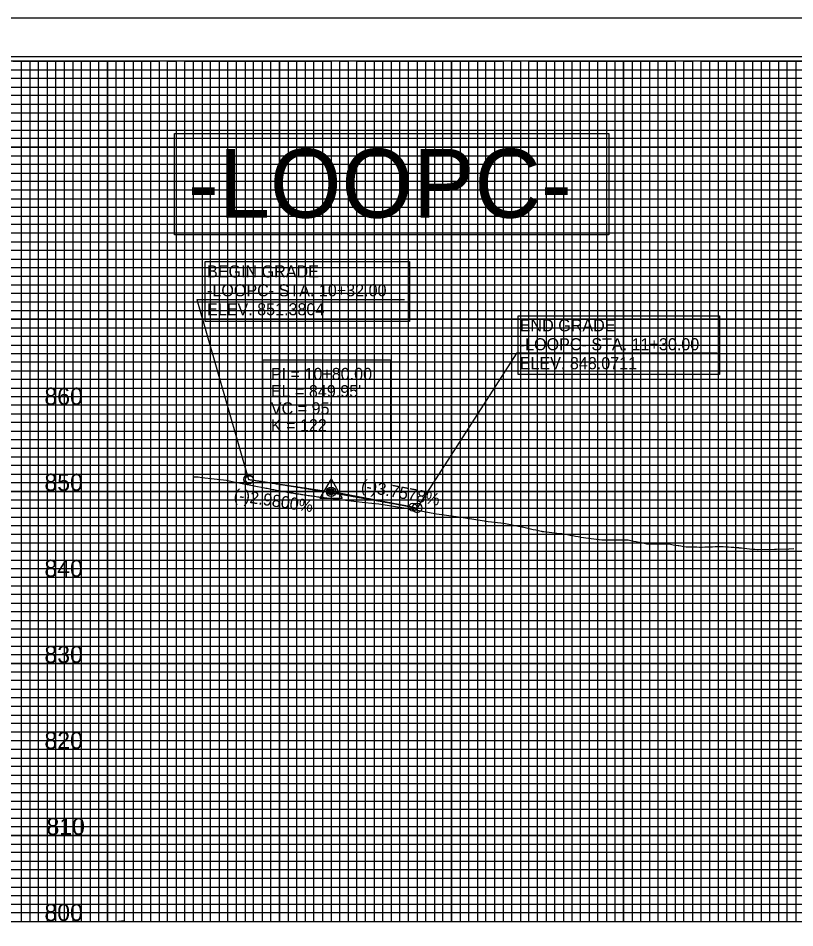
# Model space of a CAD drawing. Extents: x 570622 to 580296, y -55533 to -48575.
# Drawn here: x 571587 to 572038, y -54411 to -53883 of the extents above; entities that cross this region are included whole.
import ezdxf

# ---------------------------------------------------------------- set-up
doc = ezdxf.new("R2010")
doc.units = 0
for name, color, linetype in [('Default', 7, 'Continuous'), ('Exist Vertical Profile Ground Line', 7, 'Continuous'), ('Exist Vertical Profile Vertical Axis Label', 7, 'Continuous'), ('Prop Grid Mask', 7, 'Continuous'), ('Prop PFL VPI Symbol CELL', 7, 'Continuous'), ('Prop Vertical Profile Curve Label', 7, 'Continuous'), ('Prop Vertical Profile Grade', 7, 'Continuous'), ('Prop Vertical Profile Grade Label', 7, 'Continuous'), ('Prop VPI Label', 7, 'Continuous'), ('Sheet Cutting Line CELL', 7, 'Continuous'), ('Sheet Data Field CELL', 7, 'Continuous'), ('Sheet DOT Grid CELL', 7, 'Continuous'), ('Sheet Layout Profile Border Port 1', 7, 'Continuous'), ('Sheet Plot Border Inside CELL', 7, 'Continuous'), ('Sheet Plot Border Outside CELL', 7, 'Continuous'), ('Sheet Profile CELL', 7, 'Continuous'), ('Sheet Profile Grid Major CELL', 7, 'Continuous'), ('Sheet Profile Grid Middle CELL', 7, 'Continuous'), ('Sheet Profile Grid Minor CELL', 7, 'Continuous')]:
    doc.layers.add(name, color=color, linetype=linetype)

msp = doc.modelspace()

# ---------------------------------------------------------------- linework, layer by layer
at = {"layer": 'Exist Vertical Profile Ground Line'}
for points in [[(571688.69, -54149.28), (571691.43, -54149.22), (571691.49, -54149.22), (571693.67, -54149.67), (571707.85, -54151.26), (571711.92, -54152.09), (571729.96, -54155.63), (571730.73, -54155.79), (571731.5, -54155.94), (571732.27, -54156.08), (571733.04, -54156.23), (571733.82, -54156.38), (571734.59, -54156.53), (571735.36, -54156.68), (571736.13, -54156.82), (571736.9, -54156.97), (571737.67, -54157.11), (571738.44, -54157.25), (571739.22, -54157.4), (571739.99, -54157.54), (571740.76, -54157.68), (571741.53, -54157.82), (571742.3, -54157.96), (571743.07, -54158.09), (571743.84, -54158.23), (571743.86, -54158.23), (571744.61, -54158.37), (571745.39, -54158.5), (571746.16, -54158.64), (571746.26, -54158.65), (571746.93, -54158.76), (571747.7, -54158.88), (571748.47, -54158.99), (571749.24, -54159.11), (571750.01, -54159.22), (571750.78, -54159.34), (571751.05, -54159.38), (571751.56, -54159.45), (571752.33, -54159.57), (571753.1, -54159.69), (571753.87, -54159.8), (571754.64, -54159.92), (571755.41, -54160.03), (571756.18, -54160.14), (571756.96, -54160.26), (571757.73, -54160.37), (571758.5, -54160.47), (571759.27, -54160.58), (571760.04, -54160.69), (571760.81, -54160.79), (571761.58, -54160.9), (571762.35, -54161), (571763.13, -54161.1), (571763.9, -54161.2), (571764.63, -54161.3), (571764.67, -54161.3), (571765.44, -54161.39), (571766.21, -54161.48), (571766.98, -54161.57), (571767.75, -54161.65), (571768.52, -54161.74), (571770.69, -54161.98), (571781.89, -54163.36), (571788.29, -54164.13), (571796.44, -54164.98), (571812.14, -54167.51), (571816.7, -54168.21), (571830.01, -54170.73), (571833.08, -54171.1), (571846.76, -54173.06), (571857.6, -54174.88), (571858.26, -54174.94), (571868.98, -54176.2), (571879.58, -54178.36), (571879.84, -54178.4), (571886.17, -54179.81), (571887.7, -54180.15), (571889.23, -54180.49), (571890.77, -54180.84), (571891.07, -54180.9), (571891.37, -54180.96), (571892.3, -54181.06), (571893.83, -54181.23), (571895.36, -54181.41), (571896.9, -54181.58), (571898.43, -54181.75), (571899.96, -54181.92), (571901.5, -54182.1), (571902.46, -54182.21), (571902.83, -54182.27), (571903.03, -54182.3), (571904.56, -54182.59), (571906.09, -54182.87), (571907.63, -54183.16), (571909.16, -54183.44), (571910.69, -54183.73), (571912.23, -54184.01), (571913.33, -54184.22), (571913.68, -54184.28), (571913.76, -54184.29), (571915.29, -54184.47)], [(571915.29, -54184.47), (571916.82, -54184.66), (571918.36, -54184.85), (571919.89, -54185.04), (571921.42, -54185.23), (571922.96, -54185.42), (571924.49, -54185.6), (571926.02, -54185.79), (571926.24, -54185.82), (571926.45, -54185.84), (571927.55, -54185.84), (571929.09, -54185.85), (571930.62, -54185.85), (571932.15, -54185.86), (571933.69, -54185.87), (571935.22, -54185.87), (571936.75, -54185.88), (571938.28, -54185.88), (571939.82, -54185.88), (571940.9, -54185.89), (571940.97, -54185.9), (571941.35, -54185.97), (571942.88, -54186.28), (571944.42, -54186.58), (571945.95, -54186.88), (571947.48, -54187.18), (571947.94, -54187.27), (571949.01, -54187.49), (571950.55, -54187.81), (571951.98, -54188.11), (571952.08, -54188.11), (571952.17, -54188.12), (571953.61, -54188.12), (571955.15, -54188.12), (571955.63, -54188.12), (571956.68, -54188.13), (571958.21, -54188.14), (571959.74, -54188.16), (571961.28, -54188.17), (571962.81, -54188.19), (571964.05, -54188.2), (571964.19, -54188.2), (571964.34, -54188.22), (571965.88, -54188.46), (571967.41, -54188.7), (571968.94, -54188.94), (571970.47, -54189.19), (571970.84, -54189.24), (571972.01, -54189.43), (571973.54, -54189.69), (571975.02, -54189.93), (571975.07, -54189.93), (571975.16, -54189.93), (571976.61, -54189.95), (571978.14, -54189.97), (571979.67, -54189.99), (571981.2, -54190.02), (571982.74, -54190.04), (571984.27, -54190.07), (571984.34, -54190.07), (571984.36, -54190.07), (571985.8, -54190.02), (571987.08, -54189.97), (571987.34, -54189.96), (571988.23, -54189.93), (571988.87, -54189.91), (571990.4, -54189.87), (571991.93, -54189.82), (571993.47, -54189.78), (571994.82, -54189.74), (571994.88, -54189.74), (571995, -54189.75), (571996.53, -54189.84), (571998.07, -54189.93), (571999.6, -54190.03), (572001.13, -54190.13), (572002.66, -54190.23), (572004.2, -54190.33), (572005.5, -54190.42), (572005.51, -54190.42), (572005.73, -54190.44), (572006.54, -54190.52), (572007.26, -54190.59), (572008.8, -54190.75), (572010.33, -54190.91), (572011.86, -54191.07), (572013.39, -54191.23), (572014.93, -54191.39), (572016.46, -54191.54), (572016.72, -54191.57), (572016.8, -54191.57), (572026.45, -54191.35), (572027.45, -54191.36), (572034.71, -54191.13), (572037.64, -54190.99)]]:
    msp.add_lwpolyline(points, dxfattribs=at)
at = {"layer": 'Prop Grid Mask'}
for points in [[(571677.74, -53949.75), (571930.02, -53949.75), (571930.02, -54008.61), (571677.74, -54008.61)], [(571695.51, -54024.2), (571814.2, -54024.2), (571814.2, -54058.96), (571695.51, -54058.96)], [(571877.34, -54055.62), (571994.49, -54055.62), (571994.49, -54089.87), (571877.34, -54089.87)], [(571728.98, -54081.21), (571803.12, -54081.21), (571803.12, -54127.77), (571728.98, -54127.77)]]:
    msp.add_lwpolyline(points, close=True, dxfattribs=at)
at = {"layer": 'Prop PFL VPI Symbol CELL'}
for p, q in [((571768.68, -54150.46), (571762.23, -54161.66)), ((571768.68, -54150.46), (571775.18, -54161.66)), ((571762.23, -54161.66), (571775.18, -54161.66))]:
    msp.add_line(p, q, dxfattribs=at)
for radius in [1.75, 1.2]:
    msp.add_circle((571768.69, -54157.94), radius, dxfattribs=at)
at = {"layer": 'Prop Vertical Profile Curve Label'}
for centre in [(571721.19, -54150.86), (571816.19, -54166.87)]:
    msp.add_circle(centre, 2.25, dxfattribs=at)
at = {"layer": 'Prop Vertical Profile Grade'}
for p, q in [((571720.69, -54150.79), (571721.19, -54150.86)), ((571816.19, -54166.87), (571818.69, -54167.34))]:
    msp.add_line(p, q, dxfattribs=at)
msp.add_spline([(571721.19, -54150.86), (571723.09, -54151.15), (571724.99, -54151.43), (571726.89, -54151.72), (571728.79, -54152.01), (571730.69, -54152.3), (571732.59, -54152.59), (571734.49, -54152.88), (571736.39, -54153.18), (571738.29, -54153.47), (571740.19, -54153.77), (571742.09, -54154.07), (571743.99, -54154.37), (571745.89, -54154.67), (571747.79, -54154.97), (571749.69, -54155.28), (571751.59, -54155.58), (571753.49, -54155.89), (571755.39, -54156.2), (571757.29, -54156.51), (571759.19, -54156.82), (571761.09, -54157.14), (571762.99, -54157.45), (571764.89, -54157.77), (571766.79, -54158.08), (571768.69, -54158.4), (571770.59, -54158.72), (571772.49, -54159.05), (571774.39, -54159.37), (571776.29, -54159.7), (571778.19, -54160.02), (571780.09, -54160.35), (571781.99, -54160.68), (571783.89, -54161.01), (571785.79, -54161.34), (571787.69, -54161.68), (571789.59, -54162.01), (571791.49, -54162.35), (571793.39, -54162.69), (571795.29, -54163.03), (571797.19, -54163.37), (571799.09, -54163.71), (571800.99, -54164.06), (571802.89, -54164.4), (571804.79, -54164.75), (571806.69, -54165.1), (571808.59, -54165.45), (571810.49, -54165.8), (571812.39, -54166.16), (571814.29, -54166.51), (571816.19, -54166.87)], degree=3, dxfattribs=at)
at = {"layer": 'Prop VPI Label'}
for p, q in [((571690.66, -54046.22), (571811.31, -54046.22)), ((571690.66, -54046.22), (571720.69, -54150.79)), ((571876.67, -54077.25), (571818.69, -54167.34)), ((571876.67, -54077.25), (571992.95, -54077.25)), ((571721.19, -54150.86), (571765.97, -54157.54)), ((571816.19, -54166.87), (571771.39, -54158.45))]:
    msp.add_line(p, q, dxfattribs=at)
for centre in [(571720.69, -54150.79), (571768.69, -54157.94), (571818.69, -54167.34)]:
    msp.add_circle(centre, 2.75, dxfattribs=at)
at = {"layer": 'Sheet Cutting Line CELL'}
msp.add_line((572305.69, -53882.69), (570621.69, -53882.69), dxfattribs=at)
at = {"layer": 'Sheet DOT Grid CELL'}
for p, q in [((571588.69, -54407.69), (571588.69, -53907.69)), ((571638.69, -54407.69), (571638.69, -53907.69)), ((571688.69, -54407.69), (571688.69, -53907.69)), ((571738.69, -54407.69), (571738.69, -53907.69)), ((571788.69, -54407.69), (571788.69, -53907.69)), ((571838.69, -54407.69), (571838.69, -53907.69)), ((571888.69, -54407.69), (571888.69, -53907.69)), ((571938.69, -54407.69), (571938.69, -53907.69)), ((571988.69, -54407.69), (571988.69, -53907.69)), ((572088.64, -53957.69), (570788.69, -53957.69)), ((572088.64, -54007.69), (570788.69, -54007.69)), ((572288.69, -54057.69), (570788.69, -54057.69)), ((572288.69, -54107.69), (570788.69, -54107.69)), ((572288.69, -54157.69), (570788.69, -54157.69)), ((572288.69, -54207.69), (570788.69, -54207.69)), ((572288.69, -54257.69), (570788.69, -54257.69)), ((572288.69, -54307.69), (570788.69, -54307.69)), ((572288.69, -54357.69), (570788.69, -54357.69))]:
    msp.add_line(p, q, dxfattribs=at)
at = {"layer": 'Sheet Layout Profile Border Port 1'}
msp.add_lwpolyline([(570838.69, -53907.69), (570838.69, -54407.69), (572238.69, -54407.69), (572238.69, -54045.24), (572088.64, -54045.24), (572088.64, -53907.69)], close=True, dxfattribs=at)
at = {"layer": 'Sheet Plot Border Inside CELL'}
msp.add_lwpolyline([(570634.69, -54960.24), (572301.19, -54960.24), (572301.19, -53905.14), (570634.69, -53905.14)], close=True, dxfattribs=at)
at = {"layer": 'Sheet Plot Border Outside CELL'}
msp.add_lwpolyline([(570621.69, -54982.69), (572305.69, -54982.69), (572305.69, -53882.69), (570621.69, -53882.69)], close=True, dxfattribs=at)
at = {"layer": 'Sheet Profile CELL'}
msp.add_line((570788.69, -54407.69), (572288.69, -54407.69), dxfattribs=at)
msp.add_lwpolyline([(572288.69, -53907.69), (570788.69, -53907.69), (570788.69, -54957.69), (572288.69, -54957.69)], close=True, dxfattribs=at)
at = {"layer": 'Sheet Profile Grid Major CELL'}
for points in [[(571538.69, -54407.69), (571588.69, -54407.69), (571588.69, -53907.69), (571638.69, -53907.69), (571638.69, -54407.69), (571688.69, -54407.69), (571688.69, -53907.69), (571738.69, -53907.69), (571738.69, -54407.69), (571788.69, -54407.69), (571788.69, -53907.69), (571838.69, -53907.69), (571838.69, -54407.69), (571888.69, -54407.69), (571888.69, -53907.69), (571938.69, -53907.69), (571938.69, -54407.69), (571988.69, -54407.69), (571988.69, -53907.69), (572038.69, -53907.69), (572038.69, -54407.69), (572088.69, -54407.69), (572088.69, -53907.69), (572114.99, -53907.69)], [(570788.69, -53957.69), (572088.69, -53957.69)], [(572088.69, -54007.69), (570788.69, -54007.69), (570788.69, -54057.69), (572288.69, -54057.69)], [(572288.69, -54107.69), (570788.69, -54107.69), (570788.69, -54157.69), (572288.69, -54157.69)], [(572288.69, -54207.69), (570788.69, -54207.69), (570788.69, -54257.69), (572288.69, -54257.69)], [(572288.69, -54307.69), (570788.69, -54307.69), (570788.69, -54307.69), (570788.69, -54357.69), (572288.69, -54357.69)]]:
    msp.add_lwpolyline(points, dxfattribs=at)
at = {"layer": 'Sheet Profile Grid Middle CELL'}
msp.add_line((570788.69, -53932.69), (572088.64, -53932.69), dxfattribs=at)
for points in [[(571563.69, -54407.69), (571613.69, -54407.69), (571613.69, -53907.69), (571663.69, -53907.69), (571663.69, -54407.69), (571713.69, -54407.69), (571713.69, -53907.69), (571763.69, -53907.69), (571763.69, -54407.69), (571813.69, -54407.69), (571813.69, -53907.69), (571863.69, -53907.69), (571863.69, -54407.69), (571913.69, -54407.69), (571913.69, -53907.69), (571963.69, -53907.69), (571963.69, -54407.69), (572013.69, -54407.69), (572013.69, -53907.69), (572063.69, -53907.69), (572063.69, -54407.69), (572113.69, -54407.69), (572113.69, -54045.24)], [(572088.69, -53982.69), (570788.69, -53982.69), (570788.69, -54032.69), (572088.69, -54032.69)], [(572288.69, -54082.69), (570788.69, -54082.69), (570788.69, -54132.69), (572113.69, -54132.69)], [(572288.69, -54182.69), (570788.69, -54182.69), (570788.69, -54232.69), (572288.69, -54232.69)], [(572288.69, -54282.69), (570788.69, -54282.69), (570788.69, -54332.69), (572288.69, -54332.69)], [(572288.69, -54382.69), (570788.69, -54382.69)]]:
    msp.add_lwpolyline(points, dxfattribs=at)
at = {"layer": 'Sheet Profile Grid Minor CELL'}
for p, q in [((570838.69, -53912.69), (572088.69, -53912.69)), ((572088.69, -53917.69), (570838.69, -53918.04)), ((570838.69, -53922.69), (572088.69, -53922.69)), ((572088.64, -54042.69), (570838.69, -54042.69)), ((572238.69, -54047.69), (570838.69, -54047.69)), ((572238.69, -54052.69), (570838.69, -54052.69)), ((570838.69, -54062.69), (572238.69, -54062.69)), ((572238.69, -54067.69), (570838.69, -54067.69)), ((570838.69, -54072.69), (572238.69, -54072.69)), ((572238.69, -54092.69), (570838.69, -54092.69)), ((570838.69, -54097.69), (572238.69, -54097.69)), ((572238.69, -54117.69), (570838.69, -54117.69)), ((570838.69, -54122.69), (572238.69, -54122.69)), ((572238.69, -54142.69), (570838.69, -54142.69)), ((570838.69, -54147.69), (572238.69, -54147.69)), ((572238.69, -54152.69), (570838.69, -54152.69)), ((570838.69, -54162.69), (572238.69, -54162.69)), ((572238.69, -54167.69), (570838.69, -54167.69)), ((570838.69, -54172.69), (572238.69, -54172.69)), ((572238.69, -54177.69), (570838.69, -54177.69)), ((570838.69, -54187.69), (572238.69, -54187.69)), ((572238.69, -54192.69), (570838.69, -54192.69)), ((570838.69, -54197.69), (572238.69, -54197.69)), ((572238.69, -54202.69), (570838.69, -54202.69)), ((570838.69, -54212.69), (572238.69, -54212.69)), ((572238.69, -54217.69), (570838.69, -54217.69)), ((570838.69, -54222.69), (572238.69, -54222.69)), ((572238.69, -54227.69), (570838.69, -54227.69)), ((570838.69, -54237.69), (572238.69, -54237.69)), ((572238.69, -54242.69), (570838.69, -54242.69)), ((570838.69, -54247.69), (572238.69, -54247.69)), ((572238.69, -54252.69), (570838.69, -54252.69)), ((570838.69, -54262.69), (572238.69, -54262.69)), ((572238.69, -54267.69), (570838.69, -54267.69)), ((570838.69, -54272.69), (572238.69, -54272.69)), ((572238.69, -54277.69), (570838.69, -54277.69)), ((570838.69, -54287.69), (572238.69, -54287.69)), ((572238.69, -54292.69), (570838.69, -54292.69)), ((572238.69, -54297.69), (570838.69, -54297.69)), ((572238.69, -54302.69), (570838.69, -54302.69)), ((570838.69, -54312.69), (572238.69, -54312.69)), ((572238.69, -54317.69), (570838.69, -54317.69)), ((570838.69, -54322.69), (572238.69, -54322.69)), ((572238.69, -54327.69), (570838.69, -54327.69)), ((570838.69, -54337.69), (572238.69, -54337.69)), ((572238.69, -54342.69), (570838.69, -54342.69)), ((570838.69, -54347.69), (572238.69, -54347.69)), ((572238.69, -54352.69), (570838.69, -54352.69)), ((570838.69, -54362.69), (572238.69, -54362.69)), ((572238.69, -54367.69), (570838.69, -54367.69)), ((570838.69, -54372.69), (572238.69, -54372.69)), ((572238.69, -54377.69), (570838.69, -54377.69)), ((570838.69, -54387.69), (572238.69, -54387.69)), ((572238.69, -54392.69), (570838.69, -54392.69)), ((570838.69, -54397.69), (572238.69, -54397.69))]:
    msp.add_line(p, q, dxfattribs=at)
for points in [[(571583.69, -53907.69), (571593.69, -53907.69), (571593.69, -54407.69), (571598.69, -54407.69), (571598.69, -53907.69), (571603.69, -53907.69), (571603.69, -54407.69), (571608.69, -54407.69), (571608.69, -53907.69), (571618.69, -53907.69), (571618.69, -54407.69), (571623.69, -54407.69), (571623.69, -53907.69), (571628.69, -53907.69), (571628.69, -54407.69), (571633.69, -54407.69), (571633.69, -53907.69), (571643.69, -53907.69), (571643.69, -54407.69), (571648.39, -54407.14), (571648.69, -54407.69), (571648.69, -53907.69), (571653.69, -53907.69), (571653.69, -54407.69), (571658.69, -54407.69), (571658.69, -53907.69), (571668.69, -53907.69), (571668.69, -54407.69), (571673.69, -54407.69)], [(571673.69, -54407.69), (571673.69, -53907.69), (571678.69, -53907.69), (571678.69, -54407.69), (571683.69, -54407.69), (571683.69, -53907.69), (571693.69, -53907.69), (571693.69, -54407.69), (571698.69, -54407.69), (571698.69, -53907.69), (571703.69, -53907.69), (571703.69, -54407.69), (571708.69, -54407.69), (571708.69, -53907.69), (571718.69, -53907.69), (571718.69, -54407.69), (571723.69, -54407.69), (571723.69, -53907.69), (571728.69, -53907.69), (571728.69, -54407.69), (571733.69, -54407.69), (571733.69, -53907.69), (571743.69, -53907.69), (571743.69, -54407.69), (571748.69, -54407.69), (571748.69, -53907.69), (571753.69, -53907.69), (571753.69, -54407.69), (571758.69, -54407.69), (571758.69, -53907.69), (571768.69, -53907.69), (571768.69, -54407.69), (571773.69, -54407.69), (571773.69, -53907.69), (571778.69, -53907.69), (571778.69, -54407.69), (571783.69, -54407.69), (571783.69, -53907.69), (571793.69, -53907.69), (571793.69, -54407.69), (571798.69, -54407.69), (571798.69, -53907.69), (571803.69, -53907.69), (571803.69, -54407.69), (571808.69, -54407.69), (571808.69, -53907.69), (571818.69, -53907.69), (571818.69, -54407.69), (571823.69, -54407.69), (571823.69, -53907.69), (571828.69, -53907.69), (571828.69, -54407.69), (571833.69, -54407.69), (571833.69, -53907.69), (571843.69, -53907.69), (571843.69, -54407.69), (571848.69, -54407.69), (571848.69, -53907.69), (571853.69, -53907.69), (571853.69, -54407.69), (571858.69, -54407.69), (571858.69, -53907.69), (571868.69, -53907.69), (571868.69, -54407.69), (571873.69, -54407.69), (571873.69, -53907.69), (571878.69, -53907.69), (571878.69, -54407.69), (571883.69, -54407.69), (571883.69, -53907.69), (571893.69, -53907.69), (571893.69, -54407.69), (571898.69, -54407.69), (571898.69, -53907.69), (571903.69, -53907.69), (571903.69, -54407.69), (571908.69, -54407.69), (571908.69, -53907.69), (571918.69, -53907.69), (571918.69, -54407.69), (571923.69, -54407.69), (571923.69, -53907.69), (571928.69, -53907.69), (571928.69, -54407.69), (571933.69, -54407.69), (571933.69, -53907.69), (571943.69, -53907.69), (571943.69, -54407.69), (571948.69, -54407.69), (571948.69, -53907.69), (571953.69, -53907.69), (571953.69, -54407.69), (571958.69, -54407.69), (571958.69, -53907.69), (571968.69, -53907.69), (571968.69, -54407.69), (571973.69, -54407.69), (571973.69, -53907.69), (571978.69, -53907.69), (571978.69, -54407.69)], [(571978.69, -54407.69), (571983.69, -54407.69), (571983.69, -53907.69), (571993.69, -53907.69), (571993.69, -54407.69), (571998.69, -54407.69), (571998.69, -53907.69), (572003.69, -53907.69), (572003.69, -54407.69), (572008.69, -54407.69), (572008.69, -53907.69), (572018.69, -53907.69), (572018.69, -54407.69), (572023.69, -54407.69), (572023.69, -53907.69), (572028.69, -53907.69), (572028.69, -54407.69), (572033.69, -54407.69), (572033.69, -53907.69), (572043.69, -53907.69)], [(572088.69, -53927.69), (570838.69, -53927.69), (570838.69, -53937.69), (572088.69, -53937.69)], [(572088.64, -53942.69), (570838.69, -53942.69), (570838.69, -53947.69), (572088.69, -53947.69)], [(572088.69, -53952.69), (570838.69, -53952.69), (570838.69, -53962.69), (572088.69, -53962.69)], [(572088.69, -53967.69), (570838.69, -53967.69), (570838.69, -53972.69), (572088.69, -53972.69)], [(572088.69, -53977.69), (570838.69, -53977.69), (570838.69, -53987.69), (572088.69, -53987.69)], [(572088.69, -53992.69), (570838.69, -53992.69), (570838.69, -53997.69), (572088.69, -53997.69)], [(572088.69, -54002.69), (570838.69, -54002.69), (570838.69, -54012.69), (572088.69, -54012.69)], [(572088.69, -54017.79), (570838.79, -54017.79), (570838.79, -54022.69), (572088.69, -54022.69)], [(572088.69, -54027.69), (570838.69, -54027.69), (570838.69, -54037.69), (572088.69, -54037.69)], [(572238.69, -54077.69), (570838.69, -54077.69), (570838.69, -54087.69), (572238.69, -54087.69)], [(572238.69, -54102.69), (570838.69, -54102.69), (570838.69, -54112.69), (572238.69, -54112.69)], [(572238.69, -54127.69), (570838.69, -54127.69), (570838.69, -54137.69), (572238.69, -54137.69)], [(572238.69, -54402.69), (570838.69, -54402.69)]]:
    msp.add_lwpolyline(points, dxfattribs=at)

# ---------------------------------------------------------------- texts
at = {"layer": 'Default'}
for s, p in [('BEGIN GRADE', (571696.59, -54033.35)), ('-LOOPC- STA. 10+32.00', (571696.59, -54044.35)), ('ELEV. 851.3804', (571696.59, -54055.35)), ('END GRADE', (571878.32, -54064.7)), ('-LOOPC- STA. 11+30.00', (571878.32, -54075.7)), ('ELEV. 848.0711', (571878.32, -54086.7))]:
    msp.add_text(s, height=7, dxfattribs=at).set_placement(p)
at = {"layer": 'Exist Vertical Profile Vertical Axis Label'}
for s, p in [('860', (571602.12, -54107.44)), ('850', (571602.12, -54157.44)), ('840', (571602.12, -54207.44)), ('830', (571602.12, -54257.44)), ('820', (571602.12, -54307.44)), ('810', (571603.32, -54357.44)), ('800', (571602.12, -54407.44))]:
    msp.add_text(s, height=10, dxfattribs=at).set_placement(p)
at = {"layer": 'Prop Vertical Profile Curve Label'}
for s, p in [("VC = 95'", (571733.69, -54112.94)), ('K = 122', (571733.69, -54122.75))]:
    msp.add_text(s, height=7, dxfattribs=at).set_placement(p)
at = {"layer": 'Prop Vertical Profile Grade Label'}
for s, rotation, p in [('(-)3.7578%', 349.3588, (571785.68, -54157.47)), ('(-)2.9800%', 351.5253, (571711.8, -54163.05))]:
    msp.add_text(s, height=7, rotation=rotation, dxfattribs=at).set_placement(p)
at = {"layer": 'Prop VPI Label'}
for s, p in [('PI = 10+80.00', (571733.69, -54092.94)), ("EL = 849.95'", (571733.69, -54102.94))]:
    msp.add_text(s, height=7, dxfattribs=at).set_placement(p)
at = {"layer": 'Sheet Data Field CELL'}
msp.add_text('-LOOPC-', height=40, dxfattribs=at).set_placement((571685.57, -53998.66))

doc.saveas('drawing.dxf')
